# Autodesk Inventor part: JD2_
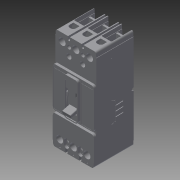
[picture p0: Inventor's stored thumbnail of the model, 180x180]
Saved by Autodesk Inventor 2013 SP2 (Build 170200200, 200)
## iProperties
Created: 2014-08
Part Number: JD2_
Material: Generic
Document SubType Name: Modeling
Designer: EM/EM
Density: 1 g/cm^3
Description: TYPE JD THERMAL MAGNETIC CIRCUIT BREAKERS TWO POLE, SERIES C
MXEDIT: false
MXINVTNRV: INV Versioned Component|JD2_|004.0
Author: EM/EM
Revision Number: 004
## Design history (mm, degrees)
derived "JD2_.iam"
node "L1"
node "L2"
node "T1"
node "T2"
sketch "Sketch1"
  geometry: C1 r 10.795 at (8.89, 11.913) reference; C2 r 10.795 at (8.89, 11.913); 1 further point
  constraints: 1 centre point, 1 coincident, 1 concentric
extrude "Extrusion1" cut sketch "Sketch1" distance "d1" = 9.525; taper "d2" = 0 deg
sketch "Sketch2"
  geometry: C1 r 6.35 at (0, 0) reference; C2 r 6.35 at (0, 0); 1 further point
  constraints: 1 centre point, 1 coincident, 1 concentric
extrude "Extrusion2" cut sketch "Sketch2" distance "d3" = 9.525; taper "d5" = 0 deg; dims "d4" = 4.7752, "d6" = 0
sketch "Sketch3"
  geometry: C1 r 10.795 at (11.493, 11.913) reference; C2 r 10.795 at (11.493, 11.913); 1 further point
  constraints: 1 centre point, 1 coincident, 1 concentric
extrude "Extrusion3" cut sketch "Sketch3" distance "d7" = 9.525; taper "d8" = 0 deg
sketch "Sketch4"
  geometry: C1 r 6.35 at (0, 0) reference; C2 r 6.35 at (0, 0); 1 further point
  constraints: 1 centre point, 1 coincident, 1 concentric
extrude "Extrusion4" cut sketch "Sketch4" distance "d9" = 9.525; taper "d11" = 0 deg; dims "d10" = 4.7752, "d12" = 0
sketch "Sketch5"
  geometry: C1 r 8.738 at (34.912, 0) reference; C2 r 8.738 at (34.912, 0); 1 further point
  constraints: 1 centre point, 1 coincident, 1 concentric
extrude "Extrusion5" cut sketch "Sketch5" distance "d13" = 9.525; taper "d15" = 0 deg; dims "d14" = 4.7752, "d16" = 0
sketch "Sketch6"
  geometry: C1 r 8.738 at (-34.938, 0) reference; C2 r 8.738 at (-34.938, 0); 1 further point
  constraints: 1 centre point, 1 coincident, 1 concentric
extrude "Extrusion6" cut sketch "Sketch6" distance "d17" = 9.525; taper "d19" = 0 deg; dims "d18" = 4.7752, "d20" = 0
body "Solid1"
node "JD2_.ipt:1"
